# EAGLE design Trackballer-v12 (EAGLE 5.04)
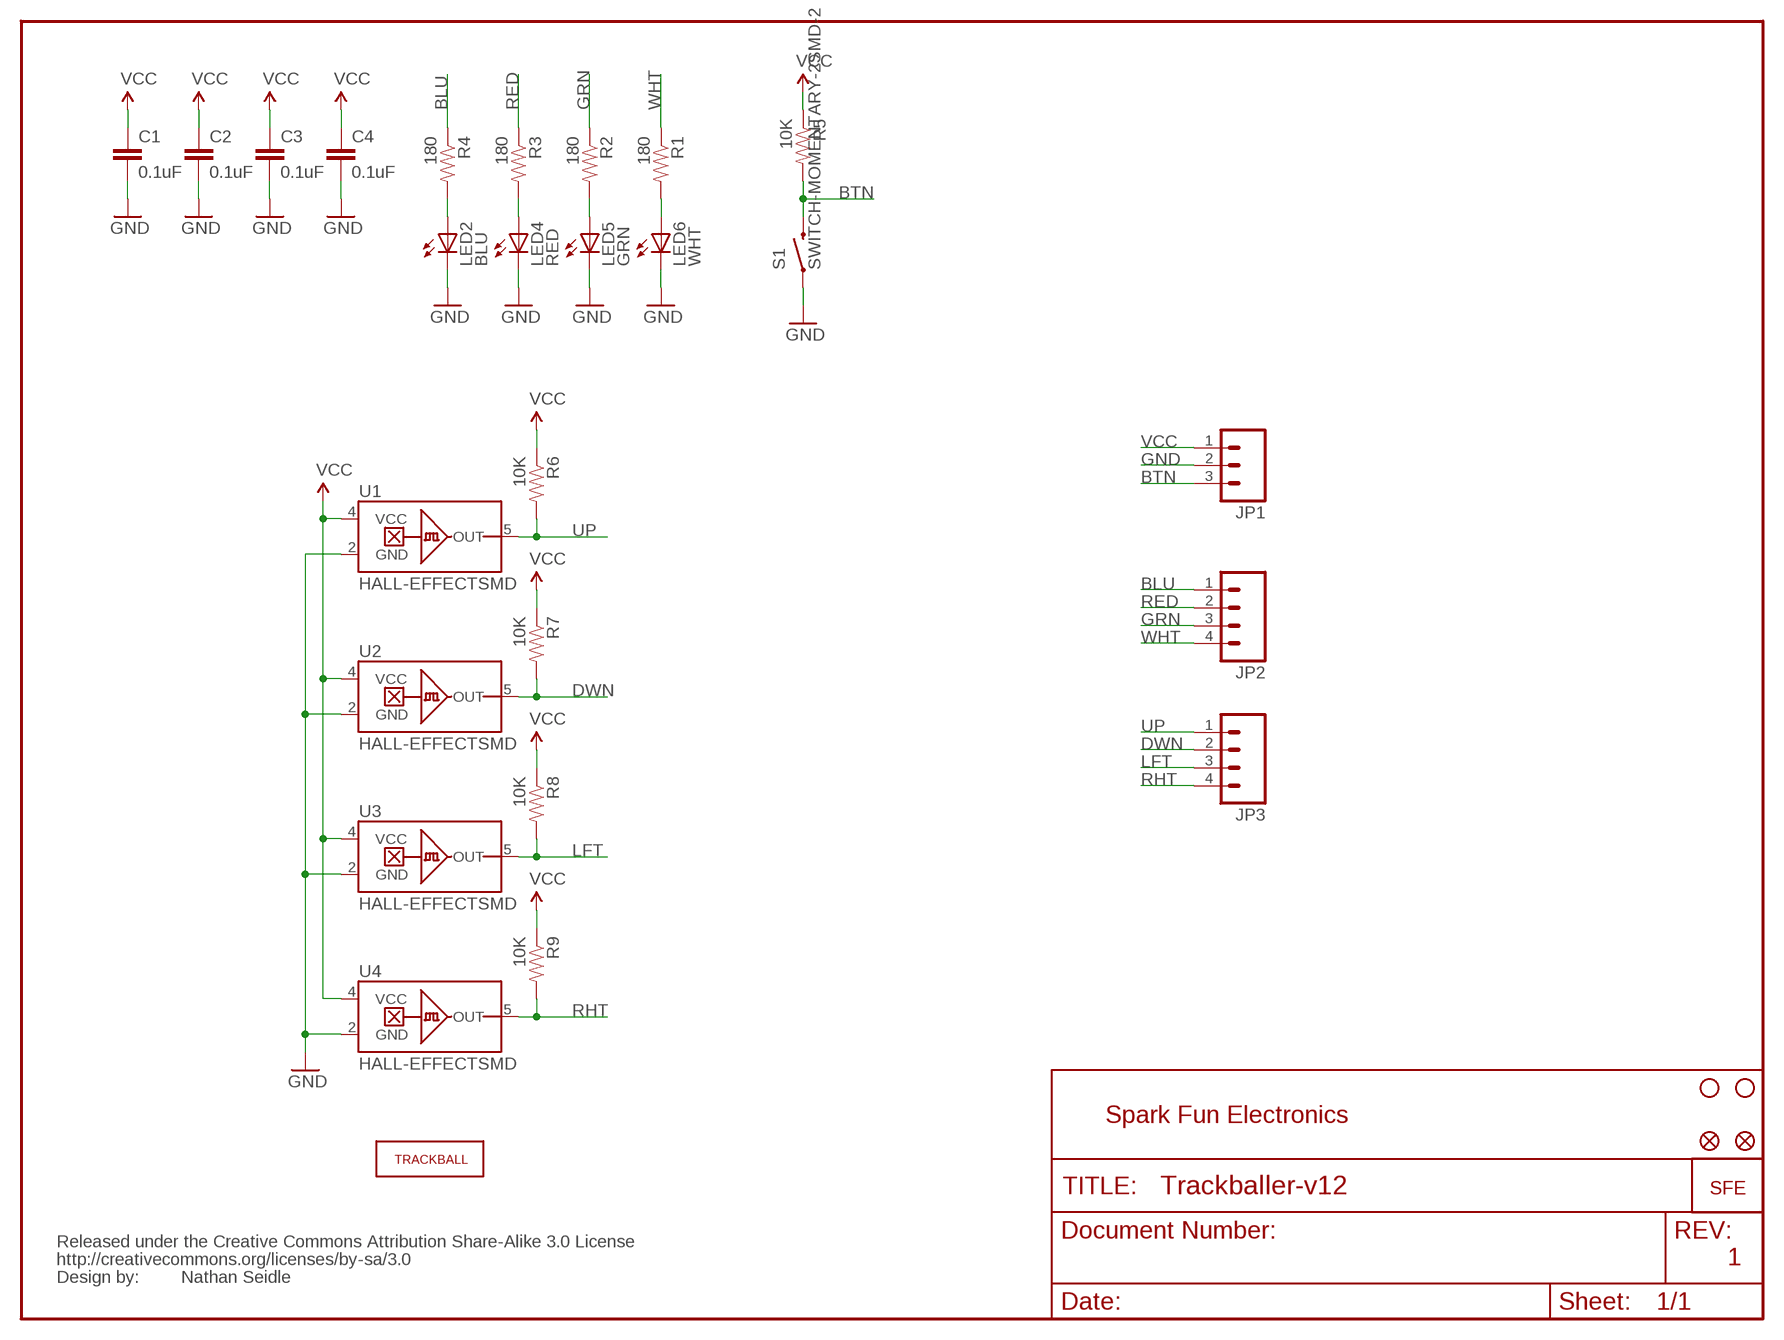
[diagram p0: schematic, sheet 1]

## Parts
C1  0.1uF  CAP0402-CAP  [0402-CAP]
C2  0.1uF  CAP0402-CAP  [0402-CAP]
C3  0.1uF  CAP0402-CAP  [0402-CAP]
C4  0.1uF  CAP0402-CAP  [0402-CAP]
E$1  FIDUCIAL1X2  [FIDUCIAL-1X2]
E$2  FIDUCIAL1X2  [FIDUCIAL-1X2]
JP1  M03PTH  [1X03]
JP2  M04PTH  [1X04]
JP3  M04PTH  [1X04]
LED2  BLU  LED0603  [LED-0603]
LED4  RED  LED0603  [LED-0603]
LED5  GRN  LED0603  [LED-0603]
LED6  WHT  LED0603  [LED-0603]
R1  180  RESISTOR0402-RES  [0402-RES]
R2  180  RESISTOR0402-RES  [0402-RES]
R3  180  RESISTOR0402-RES  [0402-RES]
R4  180  RESISTOR0402-RES  [0402-RES]
R5  10K  RESISTOR0402-RES  [0402-RES]
R6  10K  RESISTOR0402-RES  [0402-RES]
R7  10K  RESISTOR0402-RES  [0402-RES]
R8  10K  RESISTOR0402-RES  [0402-RES]
R9  10K  RESISTOR0402-RES  [0402-RES]
S1  SWITCH-MOMENTARY-2SMD-2  [TACTILE_SWITCH_SMD-2]
U1  HALL-EFFECTSMD  [SC70]
U2  HALL-EFFECTSMD  [SC70]
U3  HALL-EFFECTSMD  [SC70]
U4  HALL-EFFECTSMD  [SC70]
U$1  LOGO-SFENEW  [SFE-NEW-WEBLOGO]
U$2  TRACKBALLMECH  [TRACKBALL]
U$3  STAND-OFF  [STAND-OFF]
U$4  STAND-OFF  [STAND-OFF]
U$5  CREATIVE_COMMONS  [CREATIVE_COMMONS]

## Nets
BLU: JP2.1 R4.1
BTN: JP1.3 R5.2 S1.1
DWN: JP3.2 R7.2 U2.5(OUT)
GND: C1.2 C2.2 C3.2 C4.2 JP1.2 LED2.C LED4.C LED5.C LED6.C S1.2 U1.2(GND) U2.2(GND) U3.2(GND) U4.2(GND)
GRN: JP2.3 R2.1
LFT: JP3.3 R8.2 U3.5(OUT)
N$1: LED5.A R2.2
N$2: LED4.A R3.2
N$3: LED2.A R4.2
N$4: LED6.A R1.2
RED: JP2.2 R3.1
RHT: JP3.4 R9.2 U4.5(OUT)
UP: JP3.1 R6.2 U1.5(OUT)
VCC: C1.1 C2.1 C3.1 C4.1 JP1.1 R5.1 R6.1 R7.1 R8.1 R9.1 U1.4(VCC) U2.4(VCC) U3.4(VCC) U4.4(VCC)
WHT: JP2.4 R1.1

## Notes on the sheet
- Spark Fun Electronics
- 1
- Nathan Seidle

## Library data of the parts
C1-C4 = SparkFun:CAP: Capacitor
E$1 E$2 = SparkFun:FIDUCIAL: Fiducial Alignment Points
JP1 = SparkFun:M03: Header 3 Standard 3-pin 0.1" header. Use with straight break away headers (SKU : PRT-00116), right angle break away headers (PRT-00553), swiss pins (PRT-00743), machine pins (PRT-00117), and female headers (PRT-00115). Molex polarized connector foot print use with SKU : PRT-08232 with associated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
JP2 JP3 = SparkFun:M04: Header 4 Standard 4-pin 0.1" header. Use with straight break away headers (SKU : PRT-00116), right angle break away headers (PRT-00553), swiss pins (PRT-00743), machine pins (PRT-00117), and female headers (PRT-00115). Molex polarized connector foot print use with SKU : PRT-08231 with associated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
LED2 LED4-LED6 = SparkFun:LED: LEDs
R1-R9 = SparkFun:RESISTOR: Resistor
S1 = SparkFun:SWITCH-MOMENTARY-2
U1-U4 = SparkFun:HALL-EFFECT
U$1 = SparkFun:LOGO-SFE: Spark Fun Electronics PCB Logo
U$2 = SparkFun:TRACKBALL
U$3 U$4 = SparkFun:STAND-OFF: Stand Off
U$5 = SparkFun:CREATIVE_COMMONS

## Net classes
0 default: width 0.203 mm
1 power: width 0.203 mm

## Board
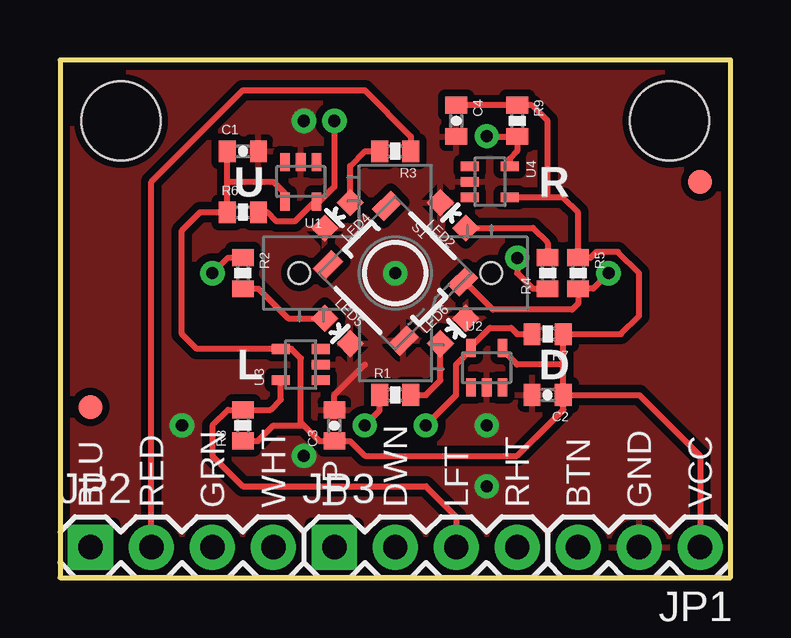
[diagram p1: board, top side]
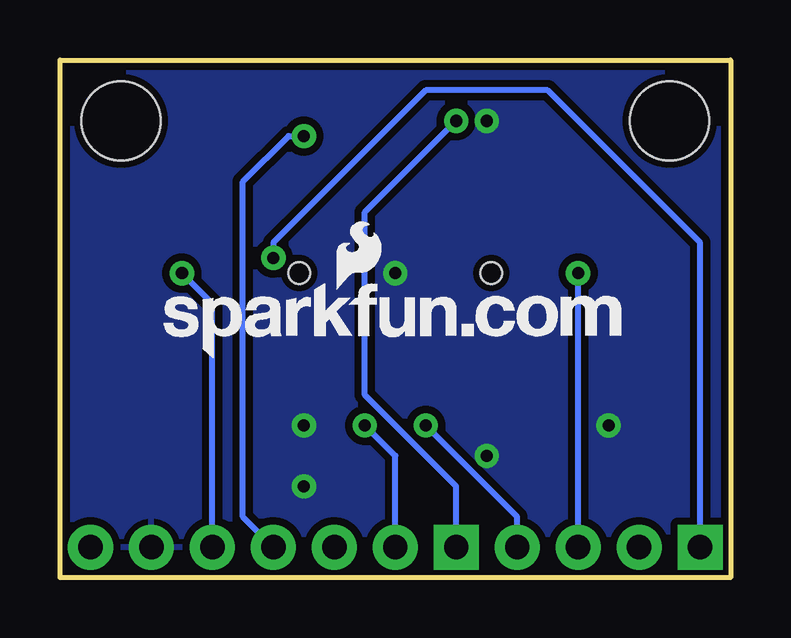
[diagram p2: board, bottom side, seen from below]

Size 27.94 x 21.59 mm. Coordinates in mm from the lower left corner, seen from the top.
Outline: 0,0 27.94,0 27.94,21.59 0,21.59 0,0
Copper layers (1*16): Top 0.035mm / dielectric 1.5mm / Bottom 0.035mm
Design rules "SparkFun": minimum track width 8mil, minimum drill 20mil, track to track 8mil, track to pad 8mil, pad to pad 8mil, via to via 8mil, smd to smd 8mil, copper to edge 10mil, drill to drill 8mil, minimum pad ring 12mil, minimum via ring 10mil, stop-mask expansion 4mil, vias tented up to drill 20mil, thermal gap 10mil

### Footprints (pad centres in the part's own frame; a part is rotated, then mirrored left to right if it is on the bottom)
0402-CAP = smd 0.7 x 0.9: 1 -0.65,0; 2 0.65,0
FIDUCIAL-1X2 = smd 1 x 1: 1 0,0
1X03 = drill 1.016 pad 1.88 round: 1 0,0; 2 2.54,0; 3 5.08,0
1X04 = drill 1.016 pad 1.88 square: 1 0,0 | drill 1.016 pad 1.88 round: 2 2.54,0; 3 5.08,0; 4 7.62,0
LED-0603 = smd 0.8 x 0.8: A 0,-0.75; C 0,0.75
0402-RES = smd 0.7 x 0.9: 1 -0.65,0; 2 0.65,0
TACTILE_SWITCH_SMD-2 = smd 0.7 x 1.1: 1 2.225,1.75; 2 2.225,-1.75; 3 -2.225,-1.75; 4 -2.225,1.75
SC70 = smd 0.4 x 0.75: 1 -0.65,-0.825; 2 0,-0.825; 3 0.65,-0.825; 4 0.65,0.825; 5 -0.65,0.825
TRACKBALL = hole 0.9: -4,0; 4,0
STAND-OFF = hole 3.302: 0,0

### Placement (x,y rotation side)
C1  7.62,17.78 0 top
C2  20.32,7.62 180 top
C3  11.43,6.35 90 top
C4  16.51,19.05 270 top
E$1  1.27,7.11 0 top
E$2  26.67,16.51 0 top
JP1  26.67,1.27 180 top
JP2  1.27,1.27 0 top
JP3  11.43,1.27 0 top
LED2  16.38,15.11 45 top
LED4  11.56,15.11 135 top
LED5  11.56,10.29 225 top
LED6  16.38,10.29 315 top
R1  13.97,7.62 0 top
R2  7.62,12.7 270 top
R3  13.97,17.78 180 top
R4  20.32,12.7 90 top
R5  21.59,12.7 270 top
R6  7.62,15.24 0 top
R7  20.32,10.16 180 top
R8  7.62,6.35 90 top
R9  19.05,19.05 270 top
S1  13.97,12.7 315 top
U1  10.03,16.51 180 top
U2  17.78,8.76 0 top
U3  10.03,8.89 90 top
U4  17.91,16.51 270 top
U$1  23.62,9.14 0 bottom
U$2  13.97,12.7 0 top
U$3  25.4,19.05 0 top
U$4  2.54,19.05 0 top
U$5  not placed on the board

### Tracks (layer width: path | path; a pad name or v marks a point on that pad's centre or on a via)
BLU  (via drill 0.51)
  Top 0.254: R4.1 19.7,12.05 19.05,12.7 v19.05,13.34
  Bottom 0.254: v19.05,13.34 19.05,13.97 12.7,20.32 7.62,20.32 1.27,13.97 JP2.1
BTN  (via drill 0.51)
  Top 0.254: v22.86,12.7 22.21,12.05 R5.2 21.59,11.43 21.34,11.18 18.03,11.18 16.85,12.36 S1.1
  Bottom 0.254: JP1.3 21.59,11.43 v22.86,12.7
DWN  (via drill 0.51)
  Top 0.254: R7.2 19.05,10.16 18.8,10.41 17.91,10.41 17.13,9.64 U2.5 17.13,9.51 16.51,8.89 16.51,7.62 v15.24,6.35
  Bottom 0.254: JP3.2 13.97,5.08 v15.24,6.35
GND  (via drill 0.51)
  Top 0.254: C3.2 11.43,7.62 12.7,8.89
  other vias: 10.16,19.05 13.97,12.7 17.78,6.35 17.78,3.81 5.08,6.35 10.16,5.08
  pour Top (isolate 0.305): 0,0 0,21.59 27.94,21.59 27.94,0
  pour Bottom (isolate 0.305): 0,0 0,21.59 27.94,21.59 27.94,0
GRN  (via drill 0.51)
  Top 0.254: R2.1 7,13.35 v6.35,12.7
  Bottom 0.254: JP2.3 v6.35,12.7
LFT
  Top 0.254: JP3.3 16.51,2.54 15.24,3.81 7.62,3.81 6.35,5.08 6.35,6.35 7,7 R8.2 8.78,7 9.21,7.43 U3.5
N$1
  Top 0.254: R2.2 8.27,12.05 9.5,10.82 LED5.A
N$2
  Top 0.254: R3.2 12.7,17.78 12.09,17.17 LED4.A
N$3
  Top 0.254: R4.2 20.32,13.97 19.71,14.58 LED2.A
N$4
  Top 0.254: R1.2 15.24,7.62 15.85,8.23 LED6.A
RED
  Top 0.254: JP2.2 3.81,16.51 7.62,20.32 12.7,20.32 14.62,18.4 R3.1
RHT  (via drill 0.51)
  Top 0.254: v17.78,18.41 17.8,18.4 R9.2 19.05,17.78 18.73,17.46 U4.5
  Bottom 0.254: JP3.4 20.32,2.54 20.32,16.51 18.41,18.41 v17.78,18.41
UP  (via drill 0.51)
  Top 0.254: v11.43,19.05 11.43,16.3 10.81,15.69 U1.5 10.61,15.69 9.78,14.86 9.02,14.86 8.64,15.24 R6.2
  Bottom 0.254: JP3.1 11.43,3.81 15.24,7.62 15.24,15.24 v11.43,19.05
VCC
  Top 0.254: JP1.1 26.67,5.08 24.13,7.62 C2.1 | C2.1 20.97,8.89 | 20.97,8.89 R7.1 23.37,10.16 24.13,10.92 24.13,12.7 23.24,13.59 22.35,13.59 22.11,13.35 R5.1 21.59,15.24 20.97,15.86 20.32,15.86 | U2.4 18.43,9.51 19.05,8.89 20.97,8.89 | 20.32,15.86 U4.4 | 20.32,15.86 20.32,19.05 19.67,19.7 R9.1 C4.1 | 6.97,16.51 R6.1 5.84,15.24 5.08,14.48 5.08,10.16 5.7,9.54 U3.4 9.64,9.54 10.03,9.14 10.03,6.48 10.16,6.35 | 6.97,16.51 C1.1 | 6.97,16.51 8.89,16.51 9.38,16.02 U1.4 | C2.1 20.97,7 19.05,5.08 12.7,5.08 12.08,5.7 C3.1 10.81,5.7 10.16,6.35 | R8.1 8.24,5.7 8.89,6.35 10.16,6.35
WHT  (via drill 0.51)
  Top 0.254: R1.1 13.32,6.97 v12.7,6.35
  Bottom 0.254: JP2.4 8.89,2.54 v12.7,6.35

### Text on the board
tPlace: U | R | L | D | BLU | RED | GRN | WHT | UP | DWN | LFT | RHT | BTN | GND | VCC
